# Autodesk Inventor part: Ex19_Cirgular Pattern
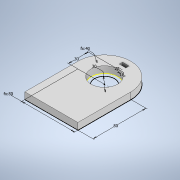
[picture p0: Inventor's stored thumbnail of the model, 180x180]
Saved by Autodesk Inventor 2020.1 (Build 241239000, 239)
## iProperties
Created: 2019-11
Part Number: Ex19_Cirgular Pattern
Material: Generic
Document SubType Name: Modeling
Designer: Synergysoft Dell02
Density: 1 g/cm^3
Appearance: Default
Author: Synergysoft Dell02
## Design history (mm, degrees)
sketch "Sketch1"
  geometry: L1 (-40, 40)-(40, 40); L2 (40, 40)-(40, -40); L3 (40, -40)-(-40, -40); L4 (-40, -40)-(-40, 40); L5 (-40, 40)-(40, -40); L6 (40, 40)-(-40, -40); C1 r 15 at (0, -40); A1 r 40 centre (0, -40) between (-40, -40) and (40, -40); 1 further point
  constraints: 12 end point, 2 centre point, 2 midpoint, 2 parallel, 2 point on circle, 1 coincident, 1 horizontal, 1 perpendicular
  dimensions: "d2" = 80 distance of L2.end L3.end (= d3); "d3" = 80 distance between parallel lines of L1 L3; "d24" = 40 radius of A1 (= 0.5 x d3); "d25" = 30 diameter of C1
extrude "Extrusion1" new body sketch "Sketch1" distance "d6" = 10; taper "d7" = 0 deg
sketch "Sketch2"
  geometry: L1 (5, -72.5)-(-5, -72.5); L2 (-5, -72.5)-(-5, -67.5); L3 (-5, -67.5)-(5, -67.5); L4 (5, -67.5)-(5, -72.5); L5 (5, -72.5)-(-5, -67.5); L6 (-5, -72.5)-(5, -67.5); C1 r 20 at (0, -40) reference; 3 further points
  constraints: 12 end point, 3 midpoint, 2 parallel, 1 horizontal, 1 perpendicular, 1 vertical alignment
  dimensions: "d8" = 10 distance of L2.end L3.end; "d9" = 5 distance of L1.end L2.end; "d10" = 30 distance of C1.centre point (0, -70)
extrude "Extrusion2" cut sketch "Sketch2" extent not by distance; stored distance "d11" = 0; taper "d12" = 0 deg
pattern_circular "Circular Pattern1" dims angle "d14" = 360 deg
sketch "Sketch3" dims "d17" = 40
  geometry: L1 (0, -40)-(0, -68); L2 (0, -40)-(33, -40); L3 (0, -40)-(10, -57.321); C1 r 1.5 at (10, -57.321); C2 r 20 at (0, -40) reference; 1 further point
  constraints: 6 end point, 1 centre point, 1 coincident, 1 horizontal, 1 vertical, 3 other
  dimensions: "d16" = 3 diameter of C1; "d18" = 60 deg angle of L2 L3
extrude "Extrusion3" cut sketch "Sketch3" distance "d19" = 10; taper "d20" = 0 deg
pattern_circular "Circular Pattern2" dims angle "d22" = 360 deg
body "Solid1"
